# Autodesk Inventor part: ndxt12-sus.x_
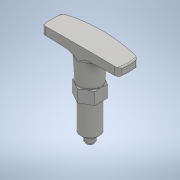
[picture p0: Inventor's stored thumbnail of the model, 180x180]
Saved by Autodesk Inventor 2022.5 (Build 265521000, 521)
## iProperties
Created: 2018-04
Part Number: ndxt12-sus.x_
Material: 一般
Document SubType Name: Modeling
Designer: imaocorp
Density: 1 g/cm^3
Appearance: 既定
Sending System: SOLIDWORKS 2016-2016286
MC: AMD64
MC_MODEL: AMD64 Family 21 Model 2 Stepping 0, AuthenticAMD
OS: Windows_NT
FRU: Parasolid Version 28.0, build 224,  7-29-2016
FORMAT: text
GUISE: transmit
KEY: ndxt12-sus
FILE: ndxt12-sus.x_t
DATE: Wed Apr 25 10:16:38 2018
Author: imaocorp
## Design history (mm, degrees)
feature "ndxt12w_01"
node "ソリッド1"
